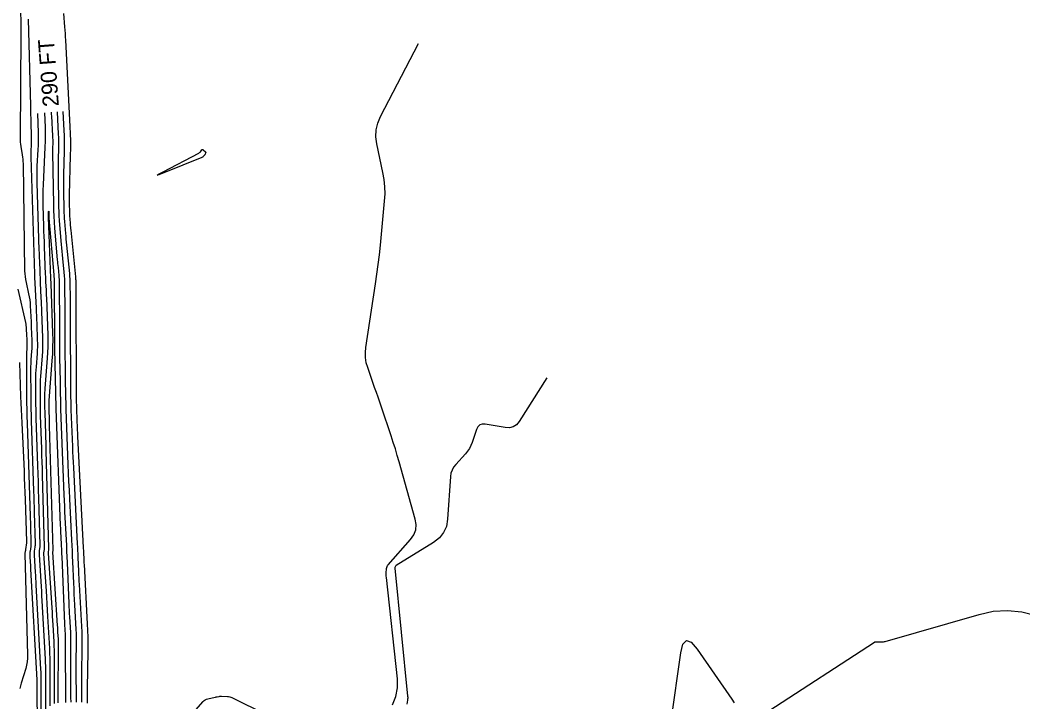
# Model space of a CAD drawing. Extents: x 1768942 to 1774819, y 723037 to 732099.
# Drawn here: x 1770861.8 to 1771237.8, y 725032.8 to 725288.6 of the extents above; entities that cross this region are included whole.
import ezdxf

# ---------------------------------------------------------------- set-up
doc = ezdxf.new("R2010")
doc.units = 0
doc.layers.add('R_Contour Annot', color=7, linetype='Continuous')
doc.layers.add('R_Contours', color=7, linetype='Continuous')

msp = doc.modelspace()

# ---------------------------------------------------------------- linework, layer by layer
at = {"layer": 'R_Contours'}
for points in [[(1770870.03, 724999.53), (1770869.68, 725034.91), (1770869.67, 725035.75), (1770869.67, 725036.59), (1770869.67, 725037.43), (1770869.67, 725038.26), (1770869.69, 725041.62), (1770869.69, 725042.46), (1770869.67, 725043.3), (1770869.64, 725044.13), (1770869.6, 725044.97), (1770867.87, 725076.67), (1770867.8, 725077.86), (1770867.73, 725079.06), (1770867.66, 725080.25), (1770867.58, 725081.44), (1770867.17, 725087.87), (1770867.16, 725088.24), (1770867.16, 725088.6), (1770867.18, 725088.97), (1770867.23, 725089.34), (1770867.43, 725090.81), (1770867.48, 725091.17), (1770867.51, 725091.54), (1770867.52, 725091.91), (1770867.52, 725092.28), (1770867.2, 725103.76), (1770867.15, 725105.8), (1770867.09, 725107.83), (1770867.02, 725109.87), (1770866.96, 725111.9), (1770866.07, 725138.32), (1770866.01, 725140.44), (1770865.96, 725142.56), (1770865.93, 725144.68), (1770865.92, 725146.8), (1770865.87, 725157.9), (1770865.88, 725158.71), (1770865.9, 725159.52), (1770865.94, 725160.34), (1770865.99, 725161.15), (1770866.24, 725164.39), (1770866.29, 725165.2), (1770866.32, 725166.01), (1770866.33, 725166.82), (1770866.31, 725167.63), (1770866.17, 725171.64), (1770866.13, 725172.58), (1770866.09, 725173.52), (1770866.05, 725174.46), (1770866.01, 725175.4), (1770865.72, 725181.42), (1770865.64, 725182.52), (1770865.52, 725183.63), (1770865.35, 725184.72), (1770865.12, 725185.81), (1770864.14, 725190.14), (1770863.93, 725191.23), (1770863.77, 725192.32), (1770863.66, 725193.42), (1770863.62, 725194.53), (1770863.01, 725234.7), (1770862.98, 725235.52), (1770862.92, 725236.33), (1770862.83, 725237.14), (1770862.71, 725237.95), (1770862.15, 725241.17), (1770862.03, 725241.98), (1770861.95, 725242.79), (1770861.9, 725243.6), (1770861.89, 725244.42), (1770862.24, 725283.58), (1770862.24, 725284.48), (1770862.24, 725285.39), (1770862.23, 725286.29), (1770862.21, 725287.19), (1770862.07, 725292.36)], [(1770878.1, 725291.01), (1770878.48, 725286.02), (1770878.57, 725284.78), (1770878.65, 725283.54), (1770878.72, 725282.31), (1770878.79, 725281.07), (1770880.49, 725248.66), (1770880.61, 725245.94), (1770880.67, 725243.22), (1770880.68, 725240.51), (1770880.63, 725237.79), (1770880.24, 725223.01), (1770880.23, 725222.24), (1770880.22, 725221.47), (1770880.22, 725220.7), (1770880.23, 725219.93), (1770880.29, 725216.42), (1770880.3, 725215.87), (1770880.32, 725215.32), (1770880.36, 725214.76), (1770880.4, 725214.21), (1770880.59, 725212), (1770880.63, 725211.45), (1770880.68, 725210.9), (1770880.74, 725210.34), (1770880.79, 725209.79), (1770882.56, 725192.2), (1770882.6, 725191.82), (1770882.62, 725191.43), (1770882.64, 725191.05), (1770882.64, 725190.67), (1770882.65, 725189.13), (1770882.65, 725188.75), (1770882.65, 725188.36), (1770882.66, 725187.98), (1770882.66, 725187.6), (1770882.73, 725170.63), (1770882.75, 725168.18), (1770882.76, 725165.73), (1770882.77, 725163.28), (1770882.78, 725160.83), (1770882.85, 725146.87), (1770882.86, 725146.5), (1770882.86, 725146.12), (1770882.87, 725145.74), (1770882.87, 725145.36), (1770882.9, 725143.85), (1770882.91, 725143.47), (1770882.92, 725143.09), (1770882.93, 725142.71), (1770882.95, 725142.34), (1770883.22, 725135.35), (1770883.25, 725134.6), (1770883.28, 725133.86), (1770883.32, 725133.11), (1770883.35, 725132.37), (1770885.47, 725090.73), (1770885.5, 725090.2), (1770885.52, 725089.67), (1770885.55, 725089.14), (1770885.57, 725088.61), (1770885.66, 725086.48), (1770885.68, 725085.95), (1770885.71, 725085.42), (1770885.73, 725084.89), (1770885.76, 725084.36), (1770886.99, 725062.13), (1770887.11, 725059.6), (1770887.18, 725057.07), (1770887.21, 725054.54), (1770887.19, 725052.01), (1770886.97, 725037.83), (1770886.97, 725037.33), (1770886.96, 725036.82), (1770886.96, 725036.32), (1770886.96, 725035.82), (1770886.98, 725033.8), (1770886.99, 725033.29), (1770886.99, 725032.79), (1770887, 725032.29)], [(1770864.81, 725288.94), (1770865.64, 725256.45), (1770865.71, 725253.76), (1770865.78, 725251.06), (1770865.95, 725244.13), (1770865.96, 725243.55), (1770865.96, 725242.98), (1770865.95, 725242.4), (1770865.92, 725241.82), (1770865.8, 725239.52), (1770865.78, 725238.94), (1770865.76, 725238.36), (1770865.76, 725237.79), (1770865.78, 725237.21), (1770867.19, 725193.27), (1770867.19, 725193.17), (1770867.19, 725193.08), (1770867.2, 725192.99), (1770867.2, 725192.9), (1770867.22, 725192.53), (1770867.22, 725192.44), (1770867.22, 725192.35), (1770867.23, 725192.25), (1770867.23, 725192.16), (1770867.79, 725180.55), (1770867.86, 725179.1), (1770867.92, 725177.64), (1770867.98, 725176.19), (1770868.03, 725174.73), (1770868.25, 725168.51), (1770868.28, 725167.25), (1770868.27, 725166), (1770868.23, 725164.74), (1770868.15, 725163.48), (1770867.76, 725158.46), (1770867.68, 725157.21), (1770867.62, 725155.95), (1770867.58, 725154.69), (1770867.58, 725153.43), (1770867.6, 725145.95), (1770867.62, 725144.28), (1770867.64, 725142.61), (1770867.68, 725140.94), (1770867.73, 725139.28), (1770868.33, 725121.37), (1770868.43, 725118.34), (1770868.52, 725115.3), (1770868.61, 725112.27), (1770868.7, 725109.24), (1770869.18, 725091.63), (1770869.18, 725091.34), (1770869.17, 725091.04), (1770869.14, 725090.75), (1770869.11, 725090.46), (1770868.95, 725089.3), (1770868.91, 725089.01), (1770868.89, 725088.71), (1770868.89, 725088.42), (1770868.9, 725088.13), (1770869.55, 725077.94), (1770869.67, 725076.14), (1770869.78, 725074.34), (1770869.88, 725072.55), (1770869.98, 725070.75), (1770871.18, 725048.87), (1770871.24, 725047.56), (1770871.29, 725046.25), (1770871.31, 725044.93), (1770871.31, 725043.62), (1770871.29, 725038.37), (1770871.28, 725037.06), (1770871.29, 725035.74), (1770871.29, 725034.43), (1770871.3, 725033.12), (1770871.54, 725008.81)], [(1771001.39, 725031.72), (1771002.68, 725034.77), (1771003.3, 725038.03), (1771003.25, 725041.48), (1770999.15, 725079.49), (1770999.12, 725079.91), (1770999.1, 725080.32), (1770999.1, 725080.73), (1770999.12, 725081.15), (1770999.24, 725082.8), (1770999.3, 725083.2), (1770999.42, 725083.58), (1770999.6, 725083.93), (1770999.85, 725084.25), (1771008.22, 725093.72), (1771009.44, 725095.46), (1771010.15, 725097.32), (1771010.32, 725099.3), (1771009.98, 725101.4), (1771003.95, 725122.84), (1771003.24, 725125.29), (1771002.5, 725127.73), (1771001.74, 725130.16), (1771000.93, 725132.58), (1770997.29, 725143.36), (1770996.66, 725145.21), (1770996.02, 725147.07), (1770995.38, 725148.92), (1770994.74, 725150.78), (1770992.14, 725158.19), (1770991.61, 725160.05), (1770991.32, 725161.93), (1770991.26, 725163.84), (1770991.44, 725165.77), (1770995.07, 725189.62), (1770995.6, 725193.25), (1770996.08, 725196.89), (1770996.51, 725200.53), (1770996.89, 725204.18), (1770998.48, 725220.64), (1770998.64, 725223.36), (1770998.59, 725226.06), (1770998.33, 725228.76), (1770997.86, 725231.43), (1770995.55, 725242.13), (1770995.2, 725244.77), (1770995.32, 725247.35), (1770995.89, 725249.87), (1770996.91, 725252.33), (1771011.13, 725279.8)], [(1770868.36, 725253.57), (1770868.55, 725246.24), (1770868.57, 725244.68), (1770868.56, 725243.11), (1770868.53, 725241.55), (1770868.46, 725239.98), (1770868.13, 725233.73), (1770868.06, 725232.17), (1770868.03, 725230.6), (1770868.03, 725229.04), (1770868.06, 725227.48), (1770868.87, 725202.31), (1770868.91, 725201.28), (1770868.94, 725200.25), (1770868.98, 725199.22), (1770869.02, 725198.19), (1770869.18, 725194.07), (1770869.23, 725193.05), (1770869.27, 725192.02), (1770869.32, 725190.99), (1770869.36, 725189.96), (1770869.63, 725184.33), (1770869.69, 725183.05), (1770869.75, 725181.77), (1770869.8, 725180.49), (1770869.85, 725179.21), (1770870.2, 725169.4), (1770870.23, 725167.69), (1770870.22, 725165.99), (1770870.16, 725164.29), (1770870.06, 725162.58), (1770869.45, 725154.8), (1770869.37, 725153.59), (1770869.31, 725152.37), (1770869.28, 725151.16), (1770869.28, 725149.95), (1770869.29, 725145.09), (1770869.3, 725143.88), (1770869.32, 725142.66), (1770869.35, 725141.45), (1770869.38, 725140.23), (1770869.8, 725127.75), (1770869.88, 725125.26), (1770869.96, 725122.78), (1770870.03, 725120.29), (1770870.1, 725117.8), (1770870.83, 725090.98), (1770870.84, 725090.77), (1770870.83, 725090.55), (1770870.81, 725090.33), (1770870.79, 725090.12), (1770870.66, 725089.25), (1770870.64, 725089.04), (1770870.63, 725088.82), (1770870.62, 725088.61), (1770870.63, 725088.39), (1770871.53, 725074.43), (1770871.68, 725072.03), (1770871.82, 725069.63), (1770871.96, 725067.23), (1770872.1, 725064.83), (1770872.76, 725052.77), (1770872.84, 725050.98), (1770872.9, 725049.2), (1770872.93, 725047.41), (1770872.94, 725045.62), (1770872.9, 725038.47), (1770872.9, 725036.69), (1770872.9, 725034.9), (1770872.91, 725033.11), (1770872.92, 725031.33)], [(1770871, 725253.77), (1770871.14, 725248.35), (1770871.18, 725245.8), (1770871.17, 725243.25), (1770871.11, 725240.7), (1770871, 725238.15), (1770870.39, 725226.7), (1770870.31, 725224.78), (1770870.27, 725222.85), (1770870.27, 725220.92), (1770870.31, 725218.99), (1770870.56, 725211.27), (1770870.62, 725209.34), (1770870.69, 725207.41), (1770870.76, 725205.48), (1770870.83, 725203.56), (1770871.25, 725193.14), (1770871.28, 725192.41), (1770871.31, 725191.69), (1770871.34, 725190.96), (1770871.38, 725190.24), (1770871.52, 725187.34), (1770871.55, 725186.62), (1770871.58, 725185.89), (1770871.61, 725185.17), (1770871.64, 725184.44), (1770872.14, 725170.28), (1770872.19, 725168.13), (1770872.17, 725165.98), (1770872.1, 725163.83), (1770871.96, 725161.68), (1770871.08, 725150.32), (1770871.03, 725149.56), (1770871, 725148.8), (1770870.98, 725148.04), (1770870.97, 725147.28), (1770870.98, 725144.23), (1770870.99, 725143.47), (1770871, 725142.71), (1770871.02, 725141.95), (1770871.04, 725141.19), (1770871.3, 725133.36), (1770871.35, 725131.81), (1770871.4, 725130.25), (1770871.45, 725128.69), (1770871.49, 725127.13), (1770872.49, 725090.33), (1770872.49, 725090.19), (1770872.49, 725090.05), (1770872.48, 725089.91), (1770872.46, 725089.77), (1770872.38, 725089.21), (1770872.37, 725089.07), (1770872.36, 725088.93), (1770872.36, 725088.79), (1770872.36, 725088.65), (1770873.68, 725068.11), (1770873.78, 725066.52), (1770873.88, 725064.92), (1770873.97, 725063.32), (1770874.06, 725061.73), (1770874.41, 725055.34), (1770874.48, 725053.74), (1770874.54, 725052.15), (1770874.56, 725050.55), (1770874.57, 725048.95), (1770874.52, 725037.68), (1770874.51, 725035.87), (1770874.51, 725034.06), (1770874.52, 725032.24)], [(1770880.9, 725032.66), (1770880.88, 725034.39), (1770880.86, 725036.13), (1770880.76, 725048.03), (1770880.76, 725048.93), (1770880.76, 725049.84), (1770880.77, 725050.74), (1770880.78, 725051.64), (1770880.83, 725055.26), (1770880.84, 725056.16), (1770880.83, 725057.07), (1770880.8, 725057.97), (1770880.76, 725058.87), (1770880.44, 725064.66), (1770880.37, 725065.93), (1770880.31, 725067.2), (1770880.25, 725068.46), (1770880.19, 725069.73), (1770879.55, 725085.12), (1770879.46, 725087.23), (1770879.36, 725089.34), (1770879.26, 725091.45), (1770879.16, 725093.56), (1770878.73, 725102), (1770878.62, 725104.11), (1770878.53, 725106.21), (1770878.43, 725108.33), (1770878.35, 725110.44), (1770877.1, 725142.61), (1770877.09, 725142.76), (1770877.09, 725142.9), (1770877.08, 725143.05), (1770877.08, 725143.2), (1770876.76, 725159.3), (1770876.75, 725159.96), (1770876.74, 725160.62), (1770876.73, 725161.28), (1770876.73, 725161.94), (1770876.71, 725164.58), (1770876.71, 725165.24), (1770876.71, 725165.9), (1770876.7, 725166.56), (1770876.7, 725167.22), (1770876.69, 725170.47), (1770876.68, 725171.23), (1770876.68, 725171.99), (1770876.67, 725172.76), (1770876.67, 725173.52), (1770876.59, 725189.83), (1770876.58, 725190.57), (1770876.55, 725191.31), (1770876.5, 725192.05), (1770876.44, 725192.78), (1770876.14, 725195.73), (1770876.07, 725196.46), (1770876, 725197.2), (1770875.93, 725197.93), (1770875.87, 725198.67), (1770874.87, 725210.51), (1770874.7, 725212.73), (1770874.57, 725214.95), (1770874.47, 725217.18), (1770874.42, 725219.4), (1770874.09, 725238.78), (1770874.09, 725239.23), (1770874.09, 725239.69), (1770874.09, 725240.14), (1770874.1, 725240.59), (1770874.15, 725242.4), (1770874.16, 725242.86), (1770874.16, 725243.31), (1770874.15, 725243.76), (1770874.13, 725244.22), (1770873.91, 725248.35), (1770873.86, 725249.19), (1770873.81, 725250.03), (1770873.76, 725250.87), (1770873.7, 725251.71), (1770873.53, 725253.96)], [(1770882.94, 725032.7), (1770882.91, 725034.3), (1770882.9, 725035.9), (1770882.84, 725042.61), (1770882.83, 725044.05), (1770882.84, 725045.5), (1770882.84, 725046.95), (1770882.86, 725048.39), (1770882.95, 725054.18), (1770882.96, 725055.62), (1770882.95, 725057.07), (1770882.91, 725058.52), (1770882.84, 725059.96), (1770882.33, 725069.23), (1770882.22, 725071.25), (1770882.11, 725073.27), (1770882.02, 725075.29), (1770881.93, 725077.32), (1770881.59, 725085.4), (1770881.5, 725087.43), (1770881.41, 725089.45), (1770881.32, 725091.47), (1770881.22, 725093.49), (1770880.43, 725109.02), (1770880.27, 725112.22), (1770880.12, 725115.43), (1770879.98, 725118.64), (1770879.85, 725121.85), (1770879.05, 725142.5), (1770879.04, 725142.73), (1770879.03, 725142.97), (1770879.03, 725143.2), (1770879.02, 725143.43), (1770878.82, 725153.27), (1770878.8, 725154.53), (1770878.78, 725155.79), (1770878.77, 725157.05), (1770878.76, 725158.3), (1770878.74, 725163.33), (1770878.73, 725164.59), (1770878.72, 725165.85), (1770878.72, 725167.1), (1770878.71, 725168.36), (1770878.68, 725174.55), (1770878.68, 725176), (1770878.67, 725177.45), (1770878.66, 725178.9), (1770878.66, 725180.35), (1770878.62, 725188.74), (1770878.6, 725190.04), (1770878.54, 725191.35), (1770878.46, 725192.65), (1770878.34, 725193.96), (1770877.82, 725199.16), (1770877.69, 725200.46), (1770877.57, 725201.76), (1770877.45, 725203.07), (1770877.34, 725204.37), (1770876.71, 725211.74), (1770876.58, 725213.41), (1770876.48, 725215.07), (1770876.41, 725216.74), (1770876.37, 725218.41), (1770876.16, 725231.2), (1770876.15, 725232.41), (1770876.15, 725233.61), (1770876.16, 725234.82), (1770876.18, 725236.03), (1770876.31, 725240.86), (1770876.33, 725242.07), (1770876.33, 725243.28), (1770876.3, 725244.49), (1770876.25, 725245.7), (1770875.81, 725254.13)], [(1770884.97, 725032.75), (1770884.95, 725033.8), (1770884.94, 725034.85), (1770884.9, 725039.06), (1770884.9, 725040.11), (1770884.9, 725041.16), (1770884.91, 725042.21), (1770884.92, 725043.27), (1770885.07, 725053.1), (1770885.09, 725055.08), (1770885.06, 725057.07), (1770885.01, 725059.06), (1770884.91, 725061.05), (1770884.04, 725076.8), (1770883.97, 725078.07), (1770883.91, 725079.35), (1770883.85, 725080.62), (1770883.79, 725081.9), (1770883.58, 725087.01), (1770883.53, 725088.28), (1770883.47, 725089.56), (1770883.41, 725090.84), (1770883.34, 725092.11), (1770881.89, 725120.69), (1770881.79, 725122.67), (1770881.7, 725124.64), (1770881.62, 725126.62), (1770881.54, 725128.6), (1770881, 725142.39), (1770880.99, 725142.71), (1770880.98, 725143.03), (1770880.97, 725143.35), (1770880.96, 725143.67), (1770880.86, 725148.97), (1770880.84, 725149.96), (1770880.82, 725150.95), (1770880.81, 725151.94), (1770880.81, 725152.93), (1770880.76, 725162.08), (1770880.75, 725163.93), (1770880.74, 725165.79), (1770880.73, 725167.64), (1770880.72, 725169.5), (1770880.67, 725180.79), (1770880.67, 725181.85), (1770880.66, 725182.91), (1770880.66, 725183.97), (1770880.65, 725185.03), (1770880.63, 725189.27), (1770880.61, 725190.33), (1770880.57, 725191.39), (1770880.5, 725192.45), (1770880.41, 725193.51), (1770879.34, 725204.12), (1770879.23, 725205.22), (1770879.13, 725206.33), (1770879.03, 725207.44), (1770878.93, 725208.55), (1770878.55, 725212.98), (1770878.47, 725214.09), (1770878.4, 725215.2), (1770878.36, 725216.31), (1770878.33, 725217.42), (1770878.21, 725224.46), (1770878.2, 725226), (1770878.19, 725227.54), (1770878.21, 725229.09), (1770878.24, 725230.63), (1770878.47, 725239.33), (1770878.5, 725241.29), (1770878.5, 725243.25), (1770878.45, 725245.21), (1770878.37, 725247.18), (1770878, 725254.3)], [(1770876.12, 725032.43), (1770876.12, 725033.21), (1770876.12, 725033.99), (1770876.12, 725034.77), (1770876.21, 725053.82), (1770876.2, 725054.46), (1770876.19, 725055.1), (1770876.17, 725055.74), (1770876.14, 725056.38), (1770876, 725058.93), (1770875.97, 725059.57), (1770875.93, 725060.21), (1770875.89, 725060.85), (1770875.85, 725061.49), (1770874.09, 725088.91), (1770874.09, 725088.98), (1770874.09, 725089.04), (1770874.09, 725089.1), (1770874.1, 725089.17), (1770874.14, 725089.43), (1770874.15, 725089.49), (1770874.15, 725089.56), (1770874.15, 725089.62), (1770874.15, 725089.69), (1770872.88, 725136.46), (1770872.86, 725137.09), (1770872.84, 725137.72), (1770872.82, 725138.35), (1770872.8, 725138.98), (1770872.7, 725142.15), (1770872.69, 725142.45), (1770872.68, 725142.76), (1770872.67, 725143.07), (1770872.67, 725143.38), (1770872.67, 725144.61), (1770872.67, 725144.92), (1770872.68, 725145.22), (1770872.69, 725145.53), (1770872.71, 725145.84), (1770873.87, 725160.78), (1770874.03, 725163.37), (1770874.12, 725165.97), (1770874.14, 725168.57), (1770874.09, 725171.16), (1770873.43, 725189.68), (1770873.42, 725189.85), (1770873.41, 725190.02), (1770873.41, 725190.19), (1770873.4, 725190.35), (1770873.37, 725191.02), (1770873.36, 725191.19), (1770873.35, 725191.36), (1770873.34, 725191.53), (1770873.34, 725191.69), (1770872.43, 725214.45), (1770872.43, 725214.51), (1770872.42, 725214.58), (1770872.42, 725214.64), (1770872.42, 725214.71), (1770872.41, 725214.96), (1770872.41, 725215.03), (1770872.41, 725215.09), (1770872.41, 725215.15), (1770872.41, 725215.22), (1770872.49, 725216.58), (1770872.5, 725216.77), (1770872.51, 725216.83), (1770872.52, 725216.76), (1770872.52, 725216.58), (1770872.54, 725215.39), (1770872.55, 725215.11), (1770872.56, 725214.83), (1770872.58, 725214.55), (1770872.6, 725214.27), (1770874.4, 725192.97), (1770874.42, 725192.8), (1770874.43, 725192.63), (1770874.45, 725192.46), (1770874.47, 725192.29), (1770874.54, 725191.61), (1770874.55, 725191.44), (1770874.56, 725191.27), (1770874.57, 725191.1), (1770874.57, 725190.93), (1770874.69, 725166.68), (1770874.69, 725166.47), (1770874.69, 725166.08), (1770874.69, 725165.96), (1770874.69, 725165.83), (1770874.69, 725165.58), (1770874.69, 725165.52), (1770874.69, 725165.46), (1770874.69, 725165.4), (1770874.69, 725165.33), (1770875.14, 725142.96), (1770875.14, 725142.9), (1770875.14, 725142.84), (1770875.14, 725142.78), (1770875.15, 725142.72), (1770876.85, 725098.94), (1770876.89, 725097.97), (1770876.93, 725097), (1770876.98, 725096.03), (1770877.02, 725095.06), (1770877.22, 725091.17), (1770877.27, 725090.2), (1770877.32, 725089.23), (1770877.36, 725088.26), (1770877.4, 725087.28), (1770878.46, 725062.13), (1770878.48, 725061.63), (1770878.5, 725061.12), (1770878.53, 725060.61), (1770878.56, 725060.11), (1770878.68, 725057.79), (1770878.7, 725057.43), (1770878.71, 725057.07), (1770878.72, 725056.7), (1770878.71, 725056.34), (1770878.69, 725054.9), (1770878.69, 725054.53), (1770878.68, 725054.17), (1770878.68, 725053.81), (1770878.69, 725053.45), (1770878.84, 725034.1), (1770878.85, 725033.36), (1770878.86, 725032.61)], [(1770860.95, 725187.66), (1770863.8, 725175.06), (1770863.92, 725174.5), (1770864, 725173.94), (1770864.07, 725173.37), (1770864.11, 725172.81), (1770864.23, 725170.24), (1770864.25, 725169.82), (1770864.27, 725169.39), (1770864.29, 725168.97), (1770864.3, 725168.55), (1770864.37, 725166.75), (1770864.37, 725166.38), (1770864.37, 725166.02), (1770864.36, 725165.65), (1770864.34, 725165.29), (1770864.22, 725163.83), (1770864.2, 725163.47), (1770864.18, 725163.1), (1770864.17, 725162.74), (1770864.17, 725162.37), (1770864.23, 725147.66), (1770864.25, 725145.08), (1770864.28, 725142.51), (1770864.34, 725139.94), (1770864.42, 725137.36), (1770865.58, 725102.44), (1770865.62, 725101.4), (1770865.65, 725100.36), (1770865.68, 725099.32), (1770865.71, 725098.28), (1770865.86, 725092.93), (1770865.86, 725092.48), (1770865.84, 725092.04), (1770865.81, 725091.59), (1770865.76, 725091.15), (1770865.51, 725089.38), (1770865.46, 725088.94), (1770865.43, 725088.5), (1770865.42, 725088.05), (1770865.44, 725087.61), (1770865.61, 725084.95), (1770865.65, 725084.36), (1770865.68, 725083.77), (1770865.72, 725083.18), (1770865.75, 725082.59), (1770868.03, 725041.07), (1770868.04, 725040.71), (1770868.06, 725040.35), (1770868.06, 725039.98), (1770868.06, 725039.62), (1770868.06, 725038.16), (1770868.05, 725037.79), (1770868.06, 725037.43), (1770868.06, 725037.07), (1770868.06, 725036.7), (1770868.51, 724990.24)], [(1770861.51, 725160.06), (1770861.99, 725147.39), (1770862.09, 725144.92), (1770862.19, 725142.45), (1770862.3, 725139.98), (1770862.41, 725137.51), (1770863.26, 725119.34), (1770863.38, 725116.69), (1770863.49, 725114.05), (1770863.59, 725111.41), (1770863.69, 725108.76), (1770864.21, 725092.98), (1770864.22, 725092.93), (1770864.22, 725092.89), (1770864.22, 725092.84), (1770864.22, 725092.8), (1770864.22, 725092.62), (1770864.22, 725092.58), (1770864.22, 725092.53), (1770864.22, 725092.49), (1770864.21, 725092.44), (1770863.86, 725089.92), (1770863.84, 725089.77), (1770863.81, 725089.63), (1770863.78, 725089.48), (1770863.74, 725089.34), (1770863.53, 725088.49), (1770863.53, 725088.48), (1770863.53, 725088.47), (1770863.52, 725088.46), (1770863.52, 725088.45), (1770863.52, 725088.4), (1770863.52, 725088.38), (1770863.53, 725088.36), (1770864.61, 725050.48), (1770864.59, 725049.17), (1770864.47, 725047.88), (1770864.25, 725046.61), (1770863.92, 725045.35), (1770862.22, 725039.77), (1770861.94, 725038.79), (1770861.67, 725037.8)], [(1771059.29, 725154.38), (1771048.88, 725137.95), (1771047.88, 725136.73), (1771046.69, 725135.95), (1771045.3, 725135.59), (1771043.73, 725135.67), (1771036.23, 725136.99), (1771035.08, 725137.03), (1771034.14, 725136.71), (1771033.42, 725136.03), (1771032.91, 725135), (1771031.32, 725130.13), (1771030.86, 725128.95), (1771030.29, 725127.84), (1771029.6, 725126.8), (1771028.79, 725125.83), (1771025.14, 725121.89), (1771024.34, 725120.88), (1771023.75, 725119.78), (1771023.36, 725118.6), (1771023.17, 725117.33), (1771022.1, 725101.33), (1771021.63, 725098.65), (1771020.6, 725096.3), (1771019.01, 725094.29), (1771016.86, 725092.61), (1771002.84, 725083.91), (1771002.6, 725083.72), (1771002.44, 725083.5), (1771002.36, 725083.23), (1771002.35, 725082.93), (1771007.11, 725034.91), (1771007.13, 725034.54), (1771007.13, 725034.17), (1771007.1, 725033.8), (1771007.04, 725033.44), (1771006.75, 725031.98)], [(1771142.53, 725029.39), (1771182.15, 725055.22), (1771182.22, 725055.26), (1771182.3, 725055.29), (1771182.38, 725055.31), (1771182.46, 725055.31), (1771182.79, 725055.31), (1771182.88, 725055.31), (1771182.96, 725055.3), (1771183.04, 725055.3), (1771183.13, 725055.3), (1771184.92, 725055.3), (1771185.24, 725055.32), (1771185.57, 725055.35), (1771185.89, 725055.41), (1771186.2, 725055.49), (1771221.36, 725065.64), (1771226.72, 725066.78), (1771232.07, 725067.1), (1771237.41, 725066.59), (1771242.73, 725065.26)], [(1771105.87, 725025.64), (1771109.52, 725051.17), (1771110.36, 725054.49), (1771111.67, 725055.84), (1771113.44, 725055.21), (1771115.68, 725052.61), (1771128.63, 725033.78), (1771129.6, 725032.5)], [(1770916.63, 725017.28), (1770930.45, 725032.97), (1770930.82, 725033.33), (1770931.24, 725033.62), (1770931.69, 725033.84), (1770932.19, 725033.99), (1770934.91, 725034.57), (1770935.11, 725034.61), (1770935.31, 725034.65), (1770935.5, 725034.69), (1770935.7, 725034.73), (1770936.49, 725034.88), (1770936.69, 725034.91), (1770936.89, 725034.94), (1770937.09, 725034.95), (1770937.29, 725034.94), (1770939.53, 725034.88), (1770939.96, 725034.84), (1770940.38, 725034.76), (1770940.79, 725034.63), (1770941.19, 725034.46), (1770979.25, 725015.56)]]:
    msp.add_lwpolyline(points, dxfattribs=at)
msp.add_lwpolyline([(1770928.96, 725238.72), (1770929.12, 725238.85), (1770929.28, 725239), (1770929.41, 725239.16), (1770929.91, 725239.87), (1770930.04, 725240), (1770930.18, 725240.06), (1770930.32, 725240.03), (1770930.48, 725239.92), (1770931.28, 725239.15), (1770931.36, 725239.05), (1770931.39, 725238.95), (1770931.4, 725238.85), (1770931.36, 725238.74), (1770931.15, 725238.27), (1770931.09, 725238.16), (1770931.03, 725238.05), (1770930.96, 725237.95), (1770930.88, 725237.85), (1770930.47, 725237.38), (1770930.37, 725237.28), (1770930.26, 725237.19), (1770930.14, 725237.12), (1770930, 725237.05), (1770915.64, 725231.25), (1770913.83, 725230.55), (1770913.2, 725230.39), (1770913.73, 725230.77), (1770915.43, 725231.69), (1770928.77, 725238.61)], close=True, dxfattribs=at)

# ---------------------------------------------------------------- texts
at = {"layer": 'R_Contour Annot'}
msp.add_text('290 FT', height=6, rotation=94.3149, dxfattribs=at).set_placement((1770876.36, 725256.28))

doc.saveas('drawing.dxf')
